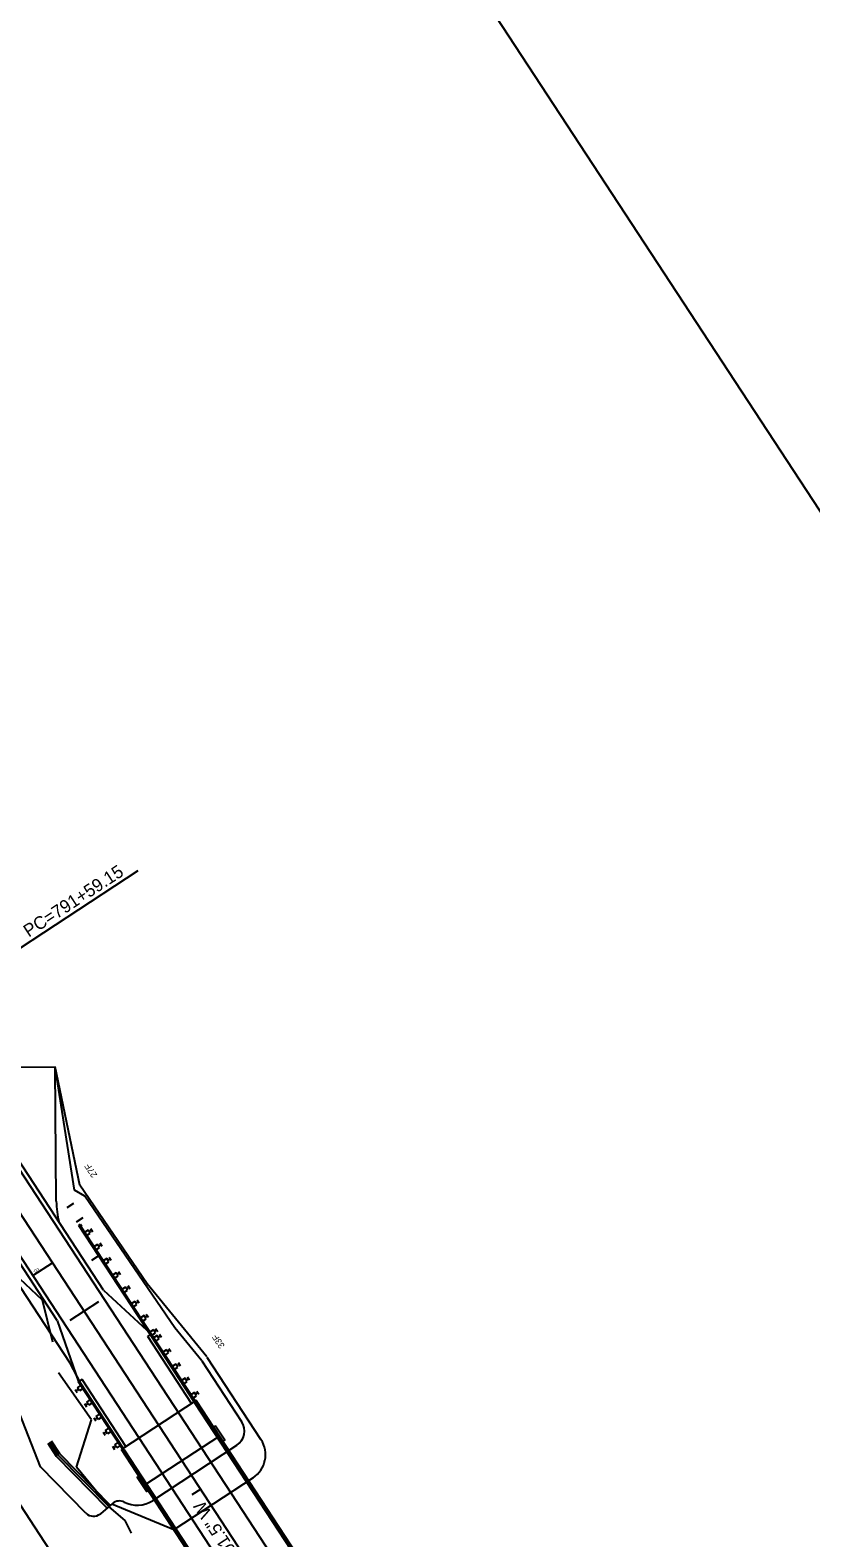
# Model space of a CAD drawing. Extents: x 1551641 to 1624343, y 1119533 to 1136600.
# Drawn here: x 1552534 to 1552901, y 1134310 to 1135018 of the extents above; entities that cross this region are included whole.
import ezdxf

# ---------------------------------------------------------------- set-up
doc = ezdxf.new("R2010")
doc.units = 0
for name, color, linetype in [('BR_CONCRETE', 7, 'Continuous'), ('RD_HC_CL_Rel', 7, 'Continuous'), ('RD_HC_Data', 7, 'Continuous'), ('RD_HC_Data_Tic', 7, 'Continuous'), ('RD_PD_ALT1_TX', 7, 'Continuous'), ('RD_PD_BOC', 7, 'Continuous'), ('RD_PD_CstnLmt', 7, 'Continuous'), ('RD_PD_CstnLmt_TX', 7, 'Continuous'), ('RD_PD_DR_ErosCtrl', 7, 'Continuous'), ('RD_PD_Driveway', 7, 'Continuous'), ('RD_PD_Final_TrvlWay', 7, 'Continuous'), ('RD_PD_GR', 7, 'Continuous'), ('RD_PD_PaveShd', 7, 'Continuous'), ('RD_PD_RW', 7, 'Continuous'), ('RD_SHT_ShtClip', 7, 'Continuous'), ('RD_Sketch1', 7, 'Continuous'), ('RD_Sketch7', 7, 'Continuous')]:
    doc.layers.add(name, color=color, linetype=linetype)

# ---------------------------------------------------------------- blocks, each defined once
blk = doc.blocks.new('Guardrail_MTBBC3_Transition')
at = {"layer": 'RD_PD_GR'}
for p, q in [((37, 0.5), (0, 0.5)), ((0, 0.5), (0, 0)), ((0, 0), (37, 0)), ((3.525, 3.75), (1.775, 3.75)), ((1.775, 0.5), (1.775, 2.5)), ((1.775, 2.5), (3.525, 2.5)), ((3.525, 0.5), (1.775, 0.5)), ((2.65, 2.5), (2.65, 3.75)), ((3.525, 2.5), (3.525, 0.5)), ((11.525, 3.75), (9.775, 3.75)), ((9.775, 0.5), (9.775, 2.5)), ((9.775, 2.5), (11.525, 2.5)), ((11.525, 0.5), (9.775, 0.5)), ((10.65, 2.5), (10.65, 3.75)), ((11.525, 2.5), (11.525, 0.5)), ((19.525, 3.75), (17.775, 3.75)), ((17.775, 0.5), (17.775, 2.5)), ((17.775, 2.5), (19.525, 2.5)), ((19.525, 0.5), (17.775, 0.5)), ((18.65, 2.5), (18.65, 3.75)), ((19.525, 2.5), (19.525, 0.5)), ((27.525, 3.75), (25.775, 3.75)), ((25.775, 0.5), (25.775, 2.5)), ((25.775, 2.5), (27.525, 2.5)), ((27.525, 0.5), (25.775, 0.5)), ((26.65, 2.5), (26.65, 3.75)), ((27.525, 2.5), (27.525, 0.5)), ((30.65, 0.5), (30.65, 0)), ((35.525, 3.75), (33.775, 3.75)), ((33.775, 0.5), (33.775, 2.5)), ((33.775, 2.5), (35.525, 2.5)), ((35.525, 0.5), (33.775, 0.5)), ((34.65, 2.5), (34.65, 3.75)), ((35.525, 2.5), (35.525, 0.5)), ((37, 0), (37, 0.5))]:
    blk.add_line(p, q, dxfattribs=at)
blk = doc.blocks.new('Guardrail_MT3_Leading_with_Buffer')
at = {"layer": 'RD_PD_GR'}
for p, q in [((1.63, 3.8), (-0.12, 3.75)), ((-0.08, 2.5), (1.67, 2.56)), ((-0.02, 0.5), (-0.08, 2.5)), ((60.95, 2.47), (-0.02, 0.5)), ((1.73, 0.56), (-0.02, 0.5)), ((-0.02, 0.5), (0, 0)), ((0, 0), (61.97, 2)), ((0.79, 2.53), (0.75, 3.78)), ((1.67, 2.56), (1.73, 0.56)), ((9.62, 4.06), (7.87, 4.01)), ((7.92, 2.76), (9.66, 2.81)), ((7.98, 0.76), (7.92, 2.76)), ((9.73, 0.81), (7.98, 0.76)), ((8.79, 2.78), (8.75, 4.03)), ((9.66, 2.81), (9.73, 0.81)), ((17.62, 4.32), (15.87, 4.26)), ((15.91, 3.01), (17.66, 3.07)), ((15.98, 1.02), (15.91, 3.01)), ((17.72, 1.07), (15.98, 1.02)), ((16.79, 3.04), (16.75, 4.29)), ((17.66, 3.07), (17.72, 1.07)), ((25.62, 4.58), (23.87, 4.52)), ((23.91, 3.27), (25.66, 3.33)), ((23.97, 1.27), (23.91, 3.27)), ((25.72, 1.33), (23.97, 1.27)), ((24.78, 3.3), (24.74, 4.55)), ((25.66, 3.33), (25.72, 1.33)), ((33.61, 4.84), (31.86, 4.78)), ((31.9, 3.53), (33.65, 3.59)), ((31.97, 1.53), (31.9, 3.53)), ((33.72, 1.59), (31.97, 1.53)), ((32.78, 3.56), (32.74, 4.81)), ((33.65, 3.59), (33.72, 1.59)), ((41.61, 5.09), (39.86, 5.04)), ((39.9, 3.79), (41.65, 3.84)), ((39.96, 1.79), (39.9, 3.79)), ((41.71, 1.85), (39.96, 1.79)), ((40.77, 3.82), (40.73, 5.07)), ((41.65, 3.84), (41.71, 1.85)), ((45.1, -2.3), (44.98, 1.45)), ((49.6, 5.35), (47.85, 5.3)), ((47.89, 4.05), (49.64, 4.1)), ((47.96, 2.05), (47.89, 4.05)), ((49.71, 2.1), (47.96, 2.05)), ((48.77, 4.07), (48.73, 5.32)), ((49.64, 4.1), (49.71, 2.1)), ((57.6, 5.61), (55.85, 5.55)), ((55.89, 4.3), (57.64, 4.36)), ((55.95, 2.31), (55.89, 4.3)), ((57.7, 2.36), (55.95, 2.31)), ((56.76, 4.33), (56.72, 5.58)), ((57.64, 4.36), (57.7, 2.36)), ((61.94, 3), (60.94, 2.97)), ((60.94, 2.97), (60.95, 2.47)), ((61.97, 2), (61.94, 3)), ((63.97, 2.06), (63.85, 5.81)), ((71.96, 2.32), (71.84, 6.07))]:
    blk.add_line(p, q, dxfattribs=at)

msp = doc.modelspace()

# ---------------------------------------------------------------- linework, layer by layer
at = {"layer": 'BR_CONCRETE'}
for p, q in [((1552612.25, 1134374.05), (1552577.12, 1134351.04)), ((1552688.98, 1134256.95), (1552612.25, 1134374.05)), ((1552688.91, 1134256.91), (1552612.18, 1134374.01)), ((1552623.22, 1134357.32), (1552588.08, 1134334.31)), ((1552653.85, 1134233.93), (1552577.12, 1134351.04)), ((1552653.92, 1134233.98), (1552577.19, 1134351.08))]:
    msp.add_line(p, q, dxfattribs=at)
for points in [[(1552688.28, 1134256.49), (1552687.53, 1134257.19), (1552611.9, 1134372.62), (1552611.56, 1134373.6)], [(1552654.55, 1134234.39), (1552654.21, 1134235.36), (1552578.58, 1134350.79), (1552577.82, 1134351.49)]]:
    msp.add_lwpolyline(points, dxfattribs=at)
for points in [[(1552620.47, 1134361.51), (1552624.86, 1134354.82), (1552625.7, 1134355.36), (1552621.31, 1134362.05)], [(1552585.34, 1134338.49), (1552589.73, 1134331.8), (1552588.89, 1134331.25), (1552584.51, 1134337.94)]]:
    msp.add_lwpolyline(points, close=True, dxfattribs=at)
at = {"layer": 'RD_HC_CL_Rel'}
msp.add_line((1552832.44, 1133999.68), (1552472.39, 1134549.2), dxfattribs=at)
at = {"layer": 'RD_HC_Data'}
msp.add_line((1552472.39, 1134549.2), (1552585.04, 1134623.01), dxfattribs=at)
at = {"layer": 'RD_HC_Data_Tic'}
for p, q in [((1552566.3, 1134420.46), (1552559.61, 1134416.08)), ((1552559.61, 1134416.08), (1552552.92, 1134411.69)), ((1552614.42, 1134332.43), (1552610.24, 1134329.69))]:
    msp.add_line(p, q, dxfattribs=at)
at = {"layer": 'RD_PD_ALT1_TX'}
msp.add_line((1552535.53, 1134432.76), (1552544.73, 1134438.79), dxfattribs=at)
at = {"layer": 'RD_PD_BOC'}
for p, q in [((1552589.52, 1134404.04), (1552591.19, 1134405.14)), ((1552610.09, 1134372.64), (1552589.52, 1134404.04)), ((1552611.77, 1134373.73), (1552591.19, 1134405.14)), ((1552558.71, 1134383.85), (1552557.04, 1134382.76)), ((1552577.61, 1134351.35), (1552557.04, 1134382.76)), ((1552579.28, 1134352.45), (1552558.71, 1134383.85))]:
    msp.add_line(p, q, dxfattribs=at)
at = {"layer": 'RD_PD_CstnLmt'}
for p, q in [((1552555.03, 1134472.85), (1552545.93, 1134530.76)), ((1552559.94, 1134470.09), (1552555.03, 1134472.85)), ((1552576.86, 1134445.31), (1552559.94, 1134470.09)), ((1552602.29, 1134408.18), (1552576.86, 1134445.31)), ((1552615.01, 1134392.6), (1552602.29, 1134408.18)), ((1552539.13, 1134342.88), (1552520.52, 1134390.46)), ((1552615.01, 1134392.6), (1552633.64, 1134364.16)), ((1552631.3, 1134352.93), (1552591.69, 1134326.98)), ((1552560.46, 1134321.17), (1552539.13, 1134342.88)), ((1552572.98, 1134325.68), (1552567.24, 1134320.85))]:
    msp.add_line(p, q, dxfattribs=at)
for centre, radius, start, end in [((1552626.86, 1134359.71), 8.11, 303.23375, 33.23375), ((1552576.2, 1134321.85), 5, 62.69034, 130.07172), ((1552584.51, 1134337.94), 13.11, 242.69034, 303.23375), ((1552564.02, 1134324.68), 5, 224.49241, 310.07172)]:
    msp.add_arc(centre, radius, start, end, dxfattribs=at)
at = {"layer": 'RD_PD_DR_ErosCtrl'}
for p, q in [((1552557.62, 1134475.27), (1552545.93, 1134530.76)), ((1552589.32, 1134428.81), (1552557.62, 1134475.27)), ((1552617.33, 1134394.49), (1552589.32, 1134428.81)), ((1552642.77, 1134355.7), (1552617.52, 1134394.24)), ((1552639.03, 1134337.71), (1552601.85, 1134313.3)), ((1552601.85, 1134313.3), (1552572.67, 1134325.42))]:
    msp.add_line(p, q, dxfattribs=at)
msp.add_arc((1552631.9, 1134348.58), 13, 303.28788, 33.23375, dxfattribs=at)
at = {"layer": 'RD_PD_Driveway'}
for p in [(1552528.93, 1134530.6), (1552546.52, 1134467.69)]:
    msp.add_line(p, (1552545.93, 1134530.76), dxfattribs=at)
msp.add_arc((1552586.52, 1134468.07), 40, 180.53797, 195.03887, dxfattribs=at)
at = {"layer": 'RD_PD_Final_TrvlWay'}
for p, q in [((1552841.65, 1134005.71), (1552481.59, 1134555.23)), ((1552823.24, 1133993.65), (1552463.19, 1134543.17))]:
    msp.add_line(p, q, dxfattribs=at)
at = {"layer": 'RD_PD_GR'}
for p, q in [((1552552.99, 1134391.51), (1552456.5, 1134538.79)), ((1552557.75, 1134382.58), (1552552.99, 1134391.51))]:
    msp.add_line(p, q, dxfattribs=at)
at = {"layer": 'RD_PD_PaveShd'}
for p, q in [((1552568.73, 1134425.88), (1552483.26, 1134556.32)), ((1552546.98, 1134411.64), (1552461.51, 1134542.07)), ((1552568.73, 1134425.88), (1552591.19, 1134405.14)), ((1552546.98, 1134411.64), (1552557.04, 1134382.76))]:
    msp.add_line(p, q, dxfattribs=at)
at = {"layer": 'RD_PD_RW'}
msp.add_line((1552647.6, 1134144.95), (1552409.65, 1134508.1), dxfattribs=at)
at = {"layer": 'RD_SHT_ShtClip'}
msp.add_line((1552560.76, 1135317.97), (1553547.26, 1133812.37), dxfattribs=at)
at = {"layer": 'RD_Sketch1'}
for p, q in [((1552546.69, 1134347.71), (1552542.67, 1134353.85)), ((1552547.47, 1134348.34), (1552543.5, 1134354.4)), ((1552548.25, 1134348.97), (1552544.34, 1134354.94)), ((1552570.64, 1134323.33), (1552546.69, 1134347.71)), ((1552571.35, 1134324.03), (1552547.47, 1134348.34)), ((1552572.06, 1134324.73), (1552548.25, 1134348.97))]:
    msp.add_line(p, q, dxfattribs=at)
at = {"layer": 'RD_Sketch7'}
for p, q in [((1552540.08, 1134421.23), (1552521.43, 1134438.78)), ((1552544.83, 1134401.48), (1552540.08, 1134421.23)), ((1552563.11, 1134364.92), (1552547.54, 1134387.09)), ((1552556.07, 1134342.75), (1552563.11, 1134364.92)), ((1552571.35, 1134324.03), (1552556.07, 1134342.75)), ((1552578.84, 1134317.74), (1552571.35, 1134324.03)), ((1552581.92, 1134311.71), (1552578.84, 1134317.74))]:
    msp.add_line(p, q, dxfattribs=at)

# ---------------------------------------------------------------- block references
at = {"layer": 'RD_PD_CstnLmt', "yscale": -1, "rotation": 123.23374605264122}
msp.add_blockref('Guardrail_MTBBC3_Transition', (1552611.35, 1134373.46), dxfattribs=at)
at = {"layer": 'RD_PD_CstnLmt', "rotation": 123.23374605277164}
msp.add_blockref('Guardrail_MTBBC3_Transition', (1552578.03, 1134351.63), dxfattribs=at)
at = {"layer": 'RD_PD_GR', "yscale": -1, "rotation": 125.08135631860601}
msp.add_blockref('Guardrail_MT3_Leading_with_Buffer', (1552591.07, 1134404.41), dxfattribs=at)

# ---------------------------------------------------------------- texts
at = {"layer": 'RD_HC_Data'}
for s, rotation, p in [('PC=791+59.15', 33.23375, (1552533.59, 1134591.42)), ('N 33%%d 14\' 01.5" W', 123.23375, (1552650.4, 1134274.52))]:
    msp.add_text(s, height=6, rotation=rotation, dxfattribs=at).set_placement(p)
at = {"layer": 'RD_PD_ALT1_TX'}
msp.add_text('-02', height=1.5, rotation=20.03896, dxfattribs=at).set_placement((1552535.85, 1134433.83))
at = {"layer": 'RD_PD_CstnLmt_TX'}
for s, p in [('27F', (1552565.91, 1134479.98)), ('33F', (1552625.88, 1134399.72))]:
    msp.add_text(s, height=3, rotation=123.23375, dxfattribs=at).set_placement(p)

doc.saveas('drawing.dxf')
